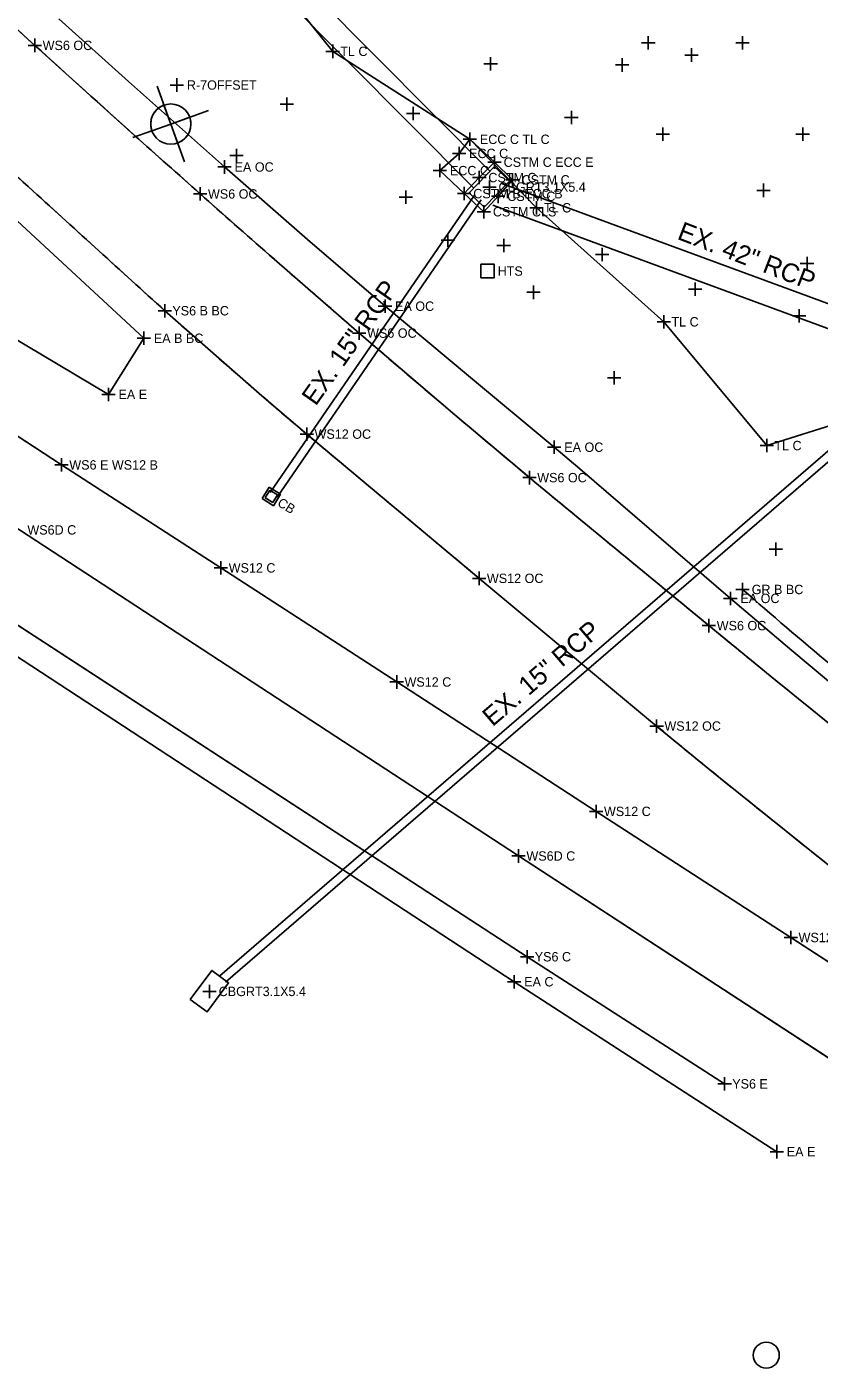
# Model space of a CAD drawing. Extents: x 1324236 to 1326110, y 459090 to 460782.
# Drawn here: x 1325909.2 to 1326027.3, y 459450.6 to 459650.5 of the extents above; entities that cross this region are included whole.
import ezdxf

# ---------------------------------------------------------------- set-up
doc = ezdxf.new("R2010")
doc.units = 0
for name, color, linetype in [('BD_X_Canopy', 7, 'Continuous'), ('DR_X_Ditch', 7, 'Continuous'), ('DR_X_Paved_Gutter', 7, 'Continuous'), ('DT_X_Contour_Major', 7, 'Continuous'), ('DV_X_Property_Line', 7, 'Continuous'), ('GT_Project_Soil_Boring', 7, 'Continuous'), ('LT_X_Poles', 7, 'Continuous'), ('PM_X_Edge_Line', 7, 'Continuous'), ('PM_X_Lane_Line', 7, 'Continuous'), ('PM_X_Parking_Lot_Stall', 7, 'Continuous'), ('PV_X_Shoulder', 7, 'Continuous'), ('RD_X_GR_Lt', 7, 'Continuous'), ('RW_X_CL', 7, 'Continuous'), ('RW_X_Esmt_SH', 7, 'Continuous'), ('UT_X_Electric', 7, 'Continuous'), ('UT_X_Telecom', 7, 'Continuous'), ('VG_X_Flower_Bed', 7, 'Continuous')]:
    doc.layers.add(name, color=color, linetype=linetype)

msp = doc.modelspace()

# ---------------------------------------------------------------- linework, layer by layer
at = {"layer": 'BD_X_Canopy'}
msp.add_lwpolyline([(1325729.36, 459692.27), (1325817.9, 459634.46), (1325908.1, 459575.52), (1325982.49, 459526.91), (1326043.74, 459486.99)], dxfattribs=at)
at = {"layer": 'DR_X_Ditch'}
for points in [[(1325722.82, 459682.9), (1325810.46, 459624.88), (1325901.15, 459565.66), (1325983.77, 459511.89), (1326013.21, 459492.94)], [(1325794.01, 459663.73), (1325823.6, 459644.37), (1325850.08, 459627.17), (1325880.87, 459607.06), (1325914.36, 459585.21)], [(1325894.93, 459661.79), (1325910.38, 459647.75), (1325910.38, 459647.75), (1325925.26, 459634.33), (1325925.26, 459634.33), (1325935.02, 459625.6), (1325935.02, 459625.6), (1325945.3, 459616.54), (1325945.3, 459616.54), (1325958.74, 459604.86), (1325958.74, 459604.86), (1325972.97, 459592.68), (1325972.97, 459592.68), (1325984.11, 459583.31), (1325984.11, 459583.31), (1325984.64, 459582.87), (1325984.64, 459582.87), (1326010.86, 459561.25), (1326010.86, 459561.25), (1326020.01, 459553.76), (1326020.01, 459553.76), (1326038.04, 459539.16), (1326038.04, 459539.16), (1326064, 459518.57)], [(1325929.76, 459608.19), (1325910.09, 459626.07), (1325910.09, 459626.07), (1325898.79, 459636.42), (1325898.79, 459636.42), (1325875.58, 459657.8)], [(1325929.76, 459608.19), (1325944.22, 459595.51), (1325944.22, 459595.51), (1325950.91, 459589.8), (1325950.91, 459589.8), (1325975.63, 459569.12), (1325975.63, 459569.12), (1325976.6, 459568.3), (1325976.6, 459568.3), (1325977.46, 459567.59), (1325977.46, 459567.59), (1326003.07, 459546.28), (1326011.53, 459539.33), (1326011.53, 459539.33), (1326028.87, 459525.4), (1326028.87, 459525.4), (1326055.21, 459504.5)], [(1325914.36, 459585.21), (1325938.12, 459569.86), (1325964.32, 459552.85), (1325994.05, 459533.56), (1326023.07, 459514.76), (1326050.18, 459497.19)]]:
    msp.add_lwpolyline(points, dxfattribs=at)
at = {"layer": 'DR_X_Paved_Gutter'}
for p, q in [((1325973.62, 459631.64), (1325975.22, 459633.75)), ((1325975.22, 459633.75), (1325978.91, 459630.34)), ((1325970.76, 459629.08), (1325973.62, 459631.64)), ((1325974.39, 459625.65), (1325970.76, 459629.08))]:
    msp.add_line(p, q, dxfattribs=at)
msp.add_lwpolyline([(1325974.39, 459625.65), (1325970.76, 459629.08), (1325973.62, 459631.64), (1325975.22, 459633.75), (1325978.91, 459630.34)], dxfattribs=at)
at = {"layer": 'DT_X_Contour_Major'}
msp.add_line((1325977.87, 459614.11), (1325977.87, 459614.11), dxfattribs=at)
msp.add_lwpolyline([(1325976.87, 459613.11), (1325976.87, 459615.11), (1325978.87, 459615.11), (1325978.87, 459613.11), (1325976.87, 459613.11)], dxfattribs=at)
at = {"layer": 'DV_X_Property_Line'}
for p, q in [((1325975.22, 459632.75), (1325975.22, 459634.75)), ((1325973.62, 459630.64), (1325973.62, 459632.64)), ((1325974.22, 459633.75), (1325976.22, 459633.75)), ((1325938.66, 459628.62), (1325938.66, 459630.62)), ((1325970.76, 459628.08), (1325970.76, 459630.08)), ((1325972.62, 459631.64), (1325974.62, 459631.64)), ((1325977.91, 459630.34), (1325979.91, 459630.34)), ((1325978.91, 459629.34), (1325978.91, 459631.34)), ((1325937.66, 459629.62), (1325939.66, 459629.62)), ((1325969.76, 459629.08), (1325971.76, 459629.08)), ((1325975.64, 459628.04), (1325977.64, 459628.04)), ((1325976.64, 459627.04), (1325976.64, 459629.04)), ((1325981.59, 459626.7), (1325981.59, 459628.7)), ((1325974.39, 459624.65), (1325974.39, 459626.65)), ((1325979.44, 459624.25), (1325979.44, 459626.25)), ((1325980.59, 459627.7), (1325982.59, 459627.7)), ((1325973.39, 459625.65), (1325975.39, 459625.65)), ((1325977.3, 459621.95), (1325977.3, 459623.95)), ((1325978.44, 459625.25), (1325980.44, 459625.25)), ((1325976.3, 459622.95), (1325978.3, 459622.95)), ((1325962.58, 459607.87), (1325962.58, 459609.87)), ((1325961.58, 459608.87), (1325963.58, 459608.87)), ((1325925.62, 459604.09), (1325927.62, 459604.09)), ((1325926.62, 459603.09), (1325926.62, 459605.09)), ((1325921.35, 459594.71), (1325921.35, 459596.71)), ((1325920.35, 459595.71), (1325922.35, 459595.71)), ((1325986.8, 459587.85), (1325988.8, 459587.85)), ((1325987.8, 459586.85), (1325987.8, 459588.85)), ((1326014.06, 459564.31), (1326014.06, 459566.31)), ((1326013.06, 459565.31), (1326015.06, 459565.31)), ((1325980.83, 459508.16), (1325982.83, 459508.16)), ((1325981.83, 459507.16), (1325981.83, 459509.16)), ((1326020.97, 459481.83), (1326020.97, 459483.83)), ((1326019.97, 459482.83), (1326021.97, 459482.83))]:
    msp.add_line(p, q, dxfattribs=at)
at = {"layer": 'GT_Project_Soil_Boring'}
for p, q in [((1325930.65, 459636.02), (1325928.62, 459641.67)), ((1325929.63, 459638.85), (1325930.65, 459636.02)), ((1325930.65, 459636.02), (1325936.29, 459638.05)), ((1325930.65, 459636.02), (1325925, 459634)), ((1325930.65, 459636.02), (1325927.82, 459635.01)), ((1325930.65, 459636.02), (1325933.47, 459637.04)), ((1325930.65, 459636.02), (1325932.67, 459630.38)), ((1325931.66, 459633.2), (1325930.65, 459636.02))]:
    msp.add_line(p, q, dxfattribs=at)
msp.add_circle((1325930.65, 459636.02), 3, dxfattribs=at)
for start, end in [(109.7344, 199.7344), (289.7344, 19.7344)]:
    msp.add_arc((1325930.65, 459636.02), 3, start, end, dxfattribs=at)
at = {"layer": 'LT_X_Poles'}
for points in [[(1325722.82, 459682.9), (1325810.46, 459624.88), (1325901.15, 459565.66), (1325983.77, 459511.89), (1326013.21, 459492.94)], [(1325794.01, 459663.73), (1325823.6, 459644.37), (1325850.08, 459627.17), (1325880.87, 459607.06), (1325914.36, 459585.21)], [(1325894.93, 459661.79), (1325910.38, 459647.75), (1325910.38, 459647.75), (1325925.26, 459634.33), (1325925.26, 459634.33), (1325935.02, 459625.6), (1325935.02, 459625.6), (1325945.3, 459616.54), (1325945.3, 459616.54), (1325958.74, 459604.86), (1325958.74, 459604.86), (1325972.97, 459592.68), (1325972.97, 459592.68), (1325984.11, 459583.31), (1325984.11, 459583.31), (1325984.64, 459582.87), (1325984.64, 459582.87), (1326010.86, 459561.25), (1326010.86, 459561.25), (1326020.01, 459553.76), (1326020.01, 459553.76), (1326038.04, 459539.16), (1326038.04, 459539.16), (1326064, 459518.57)], [(1325929.76, 459608.19), (1325910.09, 459626.07), (1325910.09, 459626.07), (1325898.79, 459636.42), (1325898.79, 459636.42), (1325875.58, 459657.8)], [(1325929.76, 459608.19), (1325944.22, 459595.51), (1325944.22, 459595.51), (1325950.91, 459589.8), (1325950.91, 459589.8), (1325975.63, 459569.12), (1325975.63, 459569.12), (1325976.6, 459568.3), (1325976.6, 459568.3), (1325977.46, 459567.59), (1325977.46, 459567.59), (1326003.07, 459546.28), (1326011.53, 459539.33), (1326011.53, 459539.33), (1326028.87, 459525.4), (1326028.87, 459525.4), (1326055.21, 459504.5)], [(1325914.36, 459585.21), (1325938.12, 459569.86), (1325964.32, 459552.85), (1325994.05, 459533.56), (1326023.07, 459514.76), (1326050.18, 459497.19)]]:
    msp.add_lwpolyline(points, dxfattribs=at)
at = {"layer": 'PM_X_Edge_Line'}
for p, q in [((1325880.87, 459607.06), (1325914.36, 459585.21)), ((1325914.36, 459585.21), (1325938.12, 459569.86)), ((1325938.12, 459569.86), (1325964.32, 459552.85)), ((1325977.46, 459567.59), (1326003.07, 459546.28)), ((1325901.15, 459565.66), (1325983.77, 459511.89)), ((1325964.32, 459552.85), (1325994.05, 459533.56)), ((1325994.05, 459533.56), (1326023.07, 459514.76)), ((1326023.07, 459514.76), (1326050.18, 459497.19)), ((1325983.77, 459511.89), (1326013.21, 459492.94))]:
    msp.add_line(p, q, dxfattribs=at)
for centre, radius, start, end in [((1328987.09, 463048.48), 4585.97, 227.60289, 227.86372), ((1330037.49, 464209.51), 6151.64, 227.863717, 228.050307), ((1327992.78, 461910.48), 3091.3, 227.36044, 227.64449), ((1327683.5, 461590.51), 2630.21, 228.05031, 228.33566), ((1332175.99, 466498.82), 9300.33, 227.644489, 227.808254), ((1326987.08, 460807.89), 1582.6, 228.33566, 228.83176), ((1327704.09, 461627.84), 2671.83, 228.83176, 229.21357), ((1327432.01, 461307.55), 2268.17, 228.52301, 229.009), ((1327565.77, 461467.51), 2460.09, 229.21357, 229.64975), ((1326254.92, 459953.03), 473.66, 229.009, 230.0725), ((1326935.38, 460725.5), 1486.44, 229.64975, 230.21089), ((1682036.19, 885047.88), 554807.44, 230.0725, 230.0758285), ((1326072.52, 459689.46), 138.14, 230.2109, 230.4948), ((1542662.38, 722385.44), 340608.92, 230.4948049, 230.5005227), ((1326527.94, 460229.1), 860.6, 230.07582, 230.16033), ((1326597.71, 460312.73), 969.51, 230.16033, 230.22586), ((1327111.53, 460896.49), 1730.41, 230.50052, 230.89209), ((1330219.48, 464719.74), 6657.54, 230.892087, 231.091714), ((1326502.88, 460146.77), 781.28, 230.22804, 231.0308), ((1328040.12, 462047.19), 3225.6, 231.0308, 231.42588)]:
    msp.add_arc(centre, radius, start, end, dxfattribs=at)
at = {"layer": 'PM_X_Lane_Line'}
for p, q in [((1325908.1, 459575.52), (1325982.49, 459526.91)), ((1325982.49, 459526.91), (1326043.74, 459486.99))]:
    msp.add_line(p, q, dxfattribs=at)
at = {"layer": 'PM_X_Parking_Lot_Stall'}
msp.add_arc((1326531.09, 460156.47), 783.16, 228.8633, 231.39317, dxfattribs=at)
at = {"layer": 'PV_X_Shoulder'}
for points in [[(1325721.22, 459678.38), (1325808.28, 459621.69), (1325899.1, 459562.26), (1325981.83, 459508.16), (1326020.97, 459482.83)], [(1325926.62, 459604.09), (1325907.09, 459622.18), (1325907.09, 459622.18), (1325896.04, 459632.5), (1325896.04, 459632.5), (1325872.66, 459654.48)], [(1325828.8, 459653.34), (1325855.9, 459636.22), (1325886.38, 459616.51), (1325921.35, 459595.71), (1325926.62, 459604.09)], [(1325913.97, 459651.72), (1325924.33, 459642.37), (1325924.33, 459642.37), (1325938.66, 459629.62), (1325938.66, 459629.62), (1325951.02, 459618.8), (1325951.02, 459618.8), (1325962.58, 459608.87), (1325962.58, 459608.87), (1325975.02, 459598.5), (1325975.02, 459598.5), (1325987.8, 459587.85), (1325987.8, 459587.85), (1325991.6, 459584.6), (1325991.6, 459584.6), (1326014.06, 459565.31), (1326014.06, 459565.31), (1326023.2, 459557.54), (1326023.2, 459557.54), (1326041.16, 459542.54), (1326041.16, 459542.54), (1326066.95, 459522.8)]]:
    msp.add_lwpolyline(points, dxfattribs=at)
at = {"layer": 'RD_X_GR_Lt'}
for p, q in [((1325954.78, 459646.86), (1325942.81, 459661.76)), ((1325975.22, 459633.75), (1325954.78, 459646.86)), ((1325985.15, 459623.54), (1325975.22, 459633.75)), ((1326004.15, 459606.54), (1325985.15, 459623.54)), ((1326019.49, 459588.09), (1326004.15, 459606.54)), ((1326035.94, 459593.3), (1326019.49, 459588.09))]:
    msp.add_line(p, q, dxfattribs=at)
at = {"layer": 'RW_X_CL'}
for p, q in [((1325910.38, 459646.75), (1325910.38, 459648.75)), ((1326000.83, 459648.13), (1326002.83, 459648.13)), ((1326001.83, 459647.13), (1326001.83, 459649.13)), ((1326014.87, 459648.13), (1326016.87, 459648.13)), ((1326015.87, 459647.13), (1326015.87, 459649.13)), ((1325909.38, 459647.75), (1325911.38, 459647.75)), ((1325978.33, 459643.99), (1325978.33, 459645.99)), ((1325997.94, 459643.83), (1325997.94, 459645.83)), ((1326007.25, 459646.31), (1326009.25, 459646.31)), ((1326008.25, 459645.31), (1326008.25, 459647.31)), ((1325977.33, 459644.99), (1325979.33, 459644.99)), ((1325996.94, 459644.83), (1325998.94, 459644.83)), ((1325930.55, 459641.84), (1325932.55, 459641.84)), ((1325931.55, 459640.84), (1325931.55, 459642.84)), ((1325947.94, 459637.98), (1325947.94, 459639.98)), ((1325946.94, 459638.98), (1325948.94, 459638.98)), ((1325966.76, 459636.6), (1325966.76, 459638.6)), ((1325990.36, 459635.98), (1325990.36, 459637.98)), ((1325965.76, 459637.6), (1325967.76, 459637.6)), ((1325989.36, 459636.98), (1325991.36, 459636.98)), ((1326002.99, 459634.51), (1326004.99, 459634.51)), ((1326003.99, 459633.51), (1326003.99, 459635.51)), ((1326023.84, 459634.52), (1326025.84, 459634.52)), ((1326024.84, 459633.52), (1326024.84, 459635.52)), ((1325940.43, 459630.32), (1325940.43, 459632.32)), ((1325939.43, 459631.32), (1325941.43, 459631.32)), ((1325935.02, 459624.6), (1325935.02, 459626.6)), ((1325965.67, 459624.13), (1325965.67, 459626.13)), ((1325977.14, 459626.63), (1325979.14, 459626.63)), ((1325978.14, 459625.63), (1325978.14, 459627.63)), ((1326018.01, 459626.14), (1326020.01, 459626.14)), ((1326019.01, 459625.14), (1326019.01, 459627.14)), ((1325934.02, 459625.6), (1325936.02, 459625.6)), ((1325964.67, 459625.13), (1325966.67, 459625.13)), ((1325970.96, 459618.7), (1325972.96, 459618.7)), ((1325971.96, 459617.7), (1325971.96, 459619.7)), ((1325979.27, 459617.92), (1325981.27, 459617.92)), ((1325980.27, 459616.92), (1325980.27, 459618.92)), ((1325993.95, 459616.56), (1325995.95, 459616.56)), ((1325994.95, 459615.56), (1325994.95, 459617.56)), ((1326025.49, 459614.21), (1326025.49, 459616.21)), ((1326024.49, 459615.21), (1326026.49, 459615.21)), ((1325984.72, 459609.94), (1325984.72, 459611.94)), ((1326008.82, 459610.4), (1326008.82, 459612.4)), ((1325983.72, 459610.94), (1325985.72, 459610.94)), ((1326007.82, 459611.4), (1326009.82, 459611.4)), ((1325928.76, 459608.19), (1325930.76, 459608.19)), ((1325929.76, 459607.19), (1325929.76, 459609.19)), ((1326024.33, 459606.43), (1326024.33, 459608.43)), ((1325958.74, 459603.86), (1325958.74, 459605.86)), ((1326023.33, 459607.43), (1326025.33, 459607.43)), ((1325957.74, 459604.86), (1325959.74, 459604.86)), ((1325995.74, 459598.18), (1325997.74, 459598.18)), ((1325996.74, 459597.18), (1325996.74, 459599.18)), ((1325949.91, 459589.8), (1325951.91, 459589.8)), ((1325950.91, 459588.8), (1325950.91, 459590.8)), ((1325914.36, 459584.21), (1325914.36, 459586.21)), ((1325913.36, 459585.21), (1325915.36, 459585.21)), ((1325984.11, 459582.31), (1325984.11, 459584.31)), ((1325983.11, 459583.31), (1325985.11, 459583.31)), ((1326019.84, 459572.65), (1326021.84, 459572.65)), ((1326020.84, 459571.65), (1326020.84, 459573.65)), ((1325937.12, 459569.86), (1325939.12, 459569.86)), ((1325938.12, 459568.86), (1325938.12, 459570.86)), ((1325975.6, 459568.3), (1325977.6, 459568.3)), ((1325976.6, 459567.3), (1325976.6, 459569.3)), ((1326010.86, 459560.25), (1326010.86, 459562.25)), ((1326009.86, 459561.25), (1326011.86, 459561.25)), ((1325964.32, 459551.85), (1325964.32, 459553.85)), ((1325963.32, 459552.85), (1325965.32, 459552.85)), ((1326002.07, 459546.28), (1326004.07, 459546.28)), ((1326003.07, 459545.28), (1326003.07, 459547.28)), ((1325994.05, 459532.56), (1325994.05, 459534.56)), ((1325993.05, 459533.56), (1325995.05, 459533.56)), ((1325982.49, 459525.91), (1325982.49, 459527.91)), ((1325981.49, 459526.91), (1325983.49, 459526.91)), ((1326022.07, 459514.76), (1326024.07, 459514.76)), ((1326023.07, 459513.76), (1326023.07, 459515.76)), ((1325982.77, 459511.89), (1325984.77, 459511.89)), ((1325983.77, 459510.89), (1325983.77, 459512.89)), ((1325935.43, 459506.72), (1325937.43, 459506.72)), ((1325936.43, 459505.72), (1325936.43, 459507.72)), ((1326013.21, 459491.94), (1326013.21, 459493.94)), ((1326012.21, 459492.94), (1326014.21, 459492.94))]:
    msp.add_line(p, q, dxfattribs=at)
at = {"layer": 'RW_X_Esmt_SH'}
for p, q in [((1325954.78, 459645.86), (1325954.78, 459647.86)), ((1325953.78, 459646.86), (1325955.78, 459646.86)), ((1325985.15, 459622.54), (1325985.15, 459624.54)), ((1325984.15, 459623.54), (1325986.15, 459623.54)), ((1326003.15, 459606.54), (1326005.15, 459606.54)), ((1326004.15, 459605.54), (1326004.15, 459607.54)), ((1326018.49, 459588.09), (1326020.49, 459588.09)), ((1326019.49, 459587.09), (1326019.49, 459589.09)), ((1326014.88, 459566.64), (1326016.88, 459566.64)), ((1326015.88, 459565.64), (1326015.88, 459567.64))]:
    msp.add_line(p, q, dxfattribs=at)
at = {"layer": 'UT_X_Electric'}
for p, q in [((1325976.64, 459628.04), (1325978.91, 459630.34)), ((1325978.91, 459630.34), (1325981.59, 459627.7)), ((1325974.39, 459625.65), (1325976.64, 459628.04)), ((1325981.59, 459627.7), (1325979.44, 459625.25)), ((1325977.3, 459622.95), (1325974.39, 459625.65)), ((1325979.44, 459625.25), (1325977.3, 459622.95)), ((1325945.3, 459581.88), (1325944.25, 459580.18)), ((1325945.3, 459581.88), (1325947, 459580.84)), ((1325945.96, 459579.13), (1325944.25, 459580.18)), ((1325944.71, 459580.29), (1325945.41, 459581.43)), ((1325945.85, 459579.59), (1325944.71, 459580.29)), ((1325945.41, 459581.43), (1325946.55, 459580.73)), ((1325946.55, 459580.73), (1325945.85, 459579.59)), ((1325947, 459580.84), (1325945.96, 459579.13))]:
    msp.add_line(p, q, dxfattribs=at)
for points in [[(1325975.14, 459625.79), (1325977.36, 459623.64), (1325981.12, 459627.52), (1325978.89, 459629.67)], [(1325933.56, 459505.5), (1325936.05, 459503.66), (1325939.27, 459507.99), (1325936.78, 459509.84)]]:
    msp.add_lwpolyline(points, close=True, dxfattribs=at)
at = {"layer": 'UT_X_Telecom'}
msp.add_circle((1326019.42, 459452.5), 1.94, dxfattribs=at)
at = {"layer": 'VG_X_Flower_Bed'}
for p, q in [((1325978.26, 459628.97), (1325795.75, 459812.7)), ((1325975.77, 459626.5), (1325793.27, 459810.24)), ((1326043.83, 459603.62), (1325979.85, 459627.22)), ((1325945.47, 459581.09), (1325975.9, 459625.43)), ((1325946.5, 459580.39), (1325976.93, 459624.72)), ((1326042.62, 459600.34), (1325978.64, 459623.94)), ((1325937.97, 459509.03), (1326042.3, 459599.11)), ((1325938.79, 459508.08), (1326043.12, 459598.16))]:
    msp.add_line(p, q, dxfattribs=at)

# ---------------------------------------------------------------- texts
at = {"layer": 'DT_X_Contour_Major'}
msp.add_text('HTS', height=1.4, dxfattribs=at).set_placement((1325979.37, 459613.41))
at = {"layer": 'DV_X_Property_Line'}
for s, p in [('ECC C TL C', (1325976.72, 459633.05)), ('ECC C', (1325975.12, 459630.94)), ('EA OC', (1325940.16, 459628.92)), ('ECC C', (1325972.26, 459628.38)), ('CSTM C ECC E', (1325980.26, 459629.64)), ('CSTM C', (1325977.99, 459627.34)), ('CSTM C', (1325982.94, 459627)), ('CSTM B ECC B', (1325975.74, 459624.95)), ('CSTM C', (1325980.8, 459624.55)), ('CSTM CLS', (1325978.66, 459622.25)), ('EA OC', (1325964.08, 459608.17)), ('EA B BC', (1325928.12, 459603.39)), ('EA E', (1325922.85, 459595.01)), ('EA OC', (1325989.3, 459587.15)), ('EA OC', (1326015.56, 459564.61)), ('EA C', (1325983.33, 459507.46)), ('EA E', (1326022.47, 459482.13))]:
    msp.add_text(s, height=1.4, dxfattribs=at).set_placement(p)
at = {"layer": 'RW_X_CL'}
for s, p in [('WS6 OC', (1325911.55, 459647.05)), ('R-7OFFSET', (1325933.05, 459641.14)), ('WS6 OC', (1325936.19, 459624.9)), ('CBGRT3.1X5.4', (1325979.5, 459625.93)), ('YS6 B BC', (1325930.88, 459607.49)), ('WS6 OC', (1325959.91, 459604.16)), ('WS12 OC', (1325952.08, 459589.1)), ('WS6 E WS12 B', (1325915.52, 459584.51)), ('WS6 OC', (1325985.27, 459582.61)), ('WS6D C', (1325909.27, 459574.82)), ('WS12 C', (1325939.28, 459569.16)), ('WS12 OC', (1325977.77, 459567.6)), ('WS6 OC', (1326012.03, 459560.55)), ('WS12 C', (1325965.49, 459552.15)), ('WS12 OC', (1326004.23, 459545.58)), ('WS12 C', (1325995.22, 459532.86)), ('WS6D C', (1325983.66, 459526.21)), ('WS12 C', (1326024.23, 459514.06)), ('YS6 C', (1325984.9, 459511.19)), ('CBGRT3.1X5.4', (1325937.79, 459506.02)), ('YS6 E', (1326014.34, 459492.24))]:
    msp.add_text(s, height=1.4, dxfattribs=at).set_placement(p)
at = {"layer": 'RW_X_Esmt_SH'}
for s, p in [('TL C', (1325955.91, 459646.16)), ('TL C', (1325986.27, 459622.84)), ('TL C', (1326005.28, 459605.84)), ('TL C', (1326020.62, 459587.39)), ('GR B BC', (1326017.24, 459565.94))]:
    msp.add_text(s, height=1.4, dxfattribs=at).set_placement(p)
at = {"layer": 'UT_X_Telecom'}
for s, height, rotation, p in [('EX. 42" RCP', 2.8, 338.8936, (1326005.99, 459618.93)), ('EX. 15" RCP', 2.8, 54.7747, (1325952.25, 459593.88)), ('CB', 1.4, 328.4633, (1325946.42, 459579.2)), ('EX. 15" RCP', 2.8, 40.6064, (1325978.61, 459546.1))]:
    msp.add_text(s, height=height, rotation=rotation, dxfattribs=at).set_placement(p)

doc.saveas('drawing.dxf')
